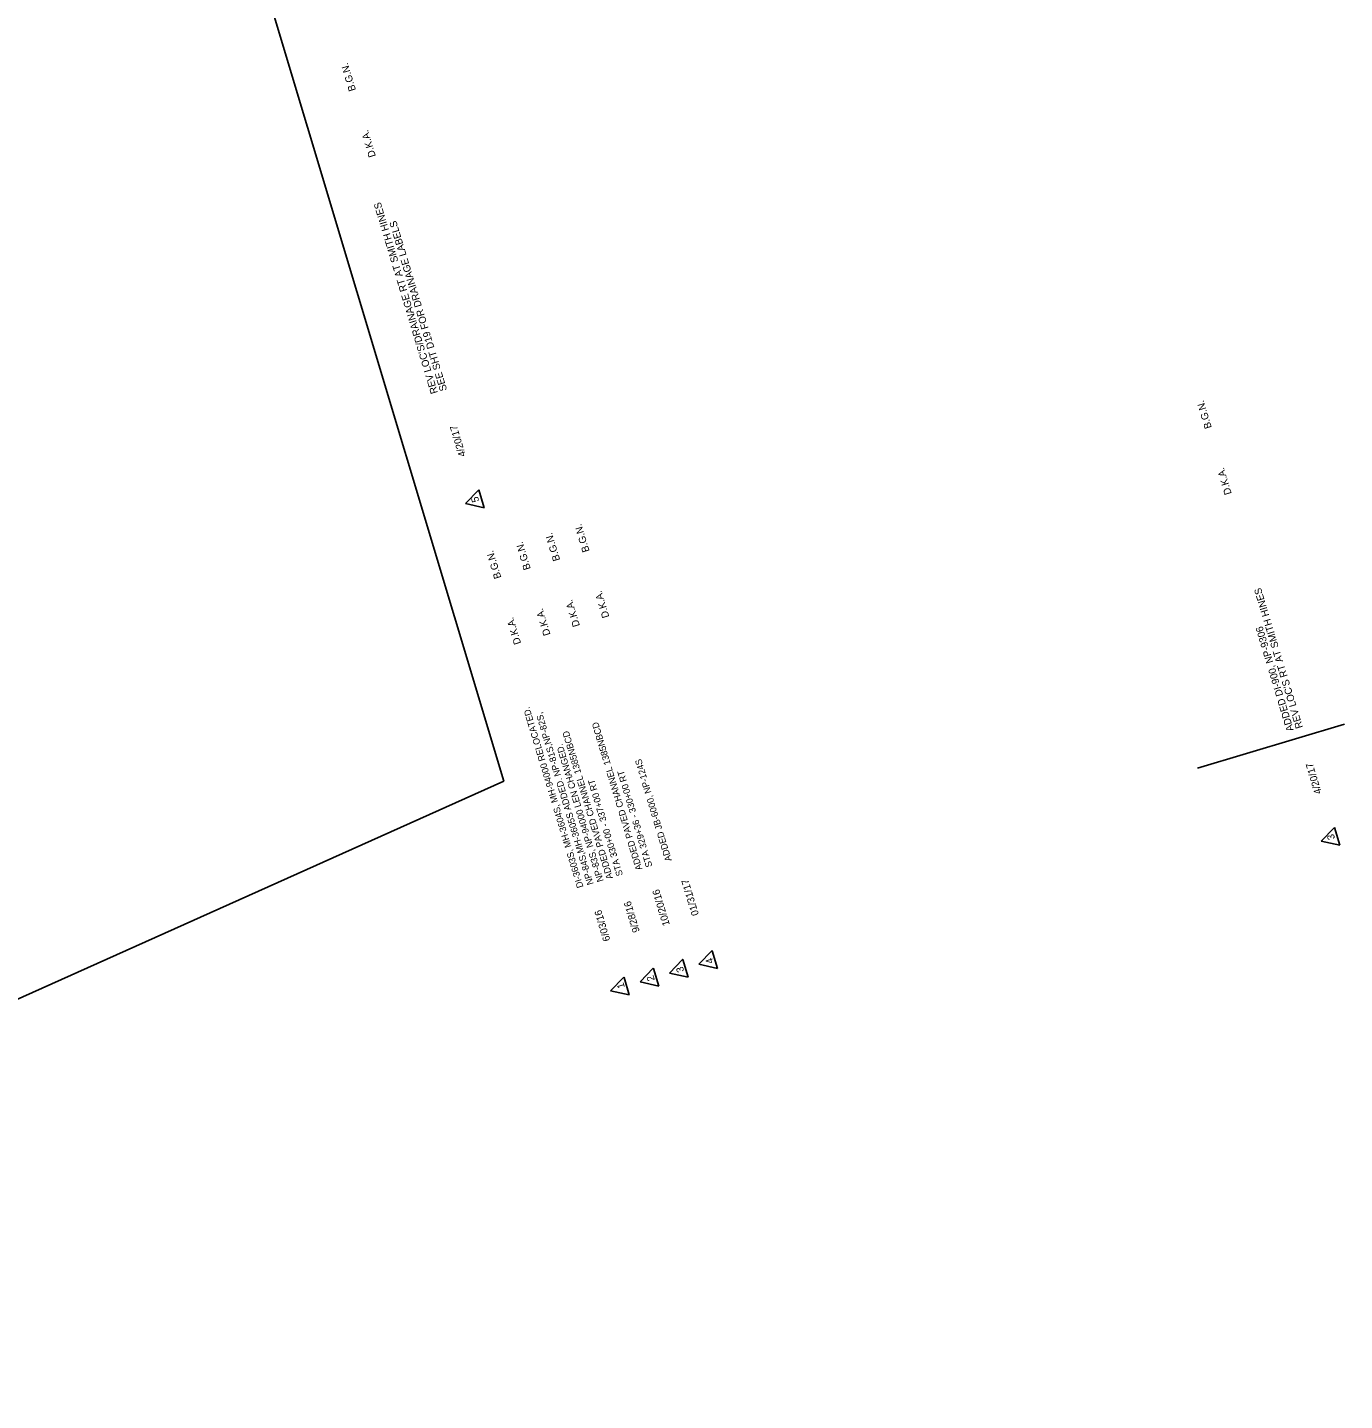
# Model space of a CAD drawing. Extents: x 1612099 to 1613927, y 1087002 to 1088782.
# Drawn here: x 1613125 to 1613927, y 1087002 to 1087838 of the extents above; entities that cross this region are included whole.
import ezdxf

# ---------------------------------------------------------------- set-up
doc = ezdxf.new("R2010")
doc.units = 0
doc.layers.add('RD_HY_Area_XP-Pre sub', color=7, linetype='Continuous')
doc.layers.add('RD_HY_Misc', color=7, linetype='Continuous')

msp = doc.modelspace()

# ---------------------------------------------------------------- linework, layer by layer
at = {"layer": 'RD_HY_Area_XP-Pre sub'}
for p, q in [((1613391.93, 1087547.97), (1613400.01, 1087556.34)), ((1613403.28, 1087545.43), (1613400.01, 1087556.34)), ((1613391.93, 1087547.97), (1613403.28, 1087545.43)), ((1613927.08, 1087413.81), (1613837.54, 1087386.89)), ((1613912.94, 1087342.52), (1613921.02, 1087350.9)), ((1613924.3, 1087339.99), (1613921.02, 1087350.9)), ((1613912.94, 1087342.52), (1613924.3, 1087339.99)), ((1613542.03, 1087275.92), (1613534.01, 1087267.61)), ((1613542.16, 1087275.74), (1613542.03, 1087275.92)), ((1613545.37, 1087265.07), (1613542.16, 1087275.74)), ((1613506.22, 1087265.16), (1613498.19, 1087256.84)), ((1613506.34, 1087264.98), (1613506.22, 1087265.16)), ((1613509.55, 1087254.31), (1613506.34, 1087264.98)), ((1613524.13, 1087270.54), (1613516.1, 1087262.22)), ((1613524.25, 1087270.36), (1613524.13, 1087270.54)), ((1613527.46, 1087259.69), (1613524.25, 1087270.36)), ((1613534.01, 1087267.61), (1613545.37, 1087265.07)), ((1613488.31, 1087259.77), (1613480.28, 1087251.45)), ((1613488.43, 1087259.59), (1613488.31, 1087259.77)), ((1613491.64, 1087248.92), (1613488.43, 1087259.59)), ((1613498.19, 1087256.84), (1613509.55, 1087254.31)), ((1613516.1, 1087262.22), (1613527.46, 1087259.69)), ((1613480.28, 1087251.45), (1613491.64, 1087248.92))]:
    msp.add_line(p, q, dxfattribs=at)
at = {"layer": 'RD_HY_Misc'}
msp.add_lwpolyline([(1612576.55, 1087001.95), (1612843.09, 1087121.93), (1613116.66, 1087245.07), (1613415.21, 1087379.03), (1613026.44, 1088673.77), (1612864.62, 1088666.55), (1612609.21, 1088637.97), (1612610.6, 1088625.86), (1612401.17, 1088591.81), (1612109.16, 1088544.34), (1612170.23, 1088342.42), (1612137.15, 1088332.42), (1612525.19, 1087049.57), (1612547, 1087056.17)], close=True, dxfattribs=at)
msp.add_lwpolyline([(1612576.55, 1087001.95), (1612843.09, 1087121.93), (1613116.66, 1087245.07), (1613415.21, 1087379.03), (1613026.44, 1088673.77), (1612864.62, 1088666.55), (1612609.21, 1088637.97), (1612610.6, 1088625.86), (1612401.17, 1088591.81), (1612109.16, 1088544.34), (1612170.23, 1088342.42), (1612137.15, 1088332.42), (1612525.19, 1087049.57), (1612547, 1087056.17)], close=True, dxfattribs=at)
msp.add_lwpolyline([(1612576.55, 1087001.95), (1612843.09, 1087121.93), (1613116.66, 1087245.07), (1613415.21, 1087379.03), (1613026.44, 1088673.77), (1612864.62, 1088666.55), (1612609.21, 1088637.97), (1612610.6, 1088625.86), (1612401.17, 1088591.81), (1612109.16, 1088544.34), (1612170.23, 1088342.42), (1612137.15, 1088332.42), (1612525.19, 1087049.57), (1612547, 1087056.17)], close=True, dxfattribs=at)
msp.add_lwpolyline([(1612576.55, 1087001.95), (1612843.09, 1087121.93), (1613116.66, 1087245.07), (1613415.21, 1087379.03), (1613026.44, 1088673.77), (1612864.62, 1088666.55), (1612609.21, 1088637.97), (1612610.6, 1088625.86), (1612401.17, 1088591.81), (1612109.16, 1088544.34), (1612170.23, 1088342.42), (1612137.15, 1088332.42), (1612525.19, 1087049.57), (1612547, 1087056.17)], close=True, dxfattribs=at)
msp.add_lwpolyline([(1612576.55, 1087001.95), (1612843.09, 1087121.93), (1613116.66, 1087245.07), (1613415.21, 1087379.03), (1613026.44, 1088673.77), (1612864.62, 1088666.55), (1612609.21, 1088637.97), (1612610.6, 1088625.86), (1612401.17, 1088591.81), (1612109.16, 1088544.34), (1612170.23, 1088342.42), (1612137.15, 1088332.42), (1612525.19, 1087049.57), (1612547, 1087056.17)], close=True, dxfattribs=at)
msp.add_lwpolyline([(1612576.55, 1087001.95), (1612843.09, 1087121.93), (1613116.66, 1087245.07), (1613415.21, 1087379.03), (1613026.44, 1088673.77), (1612864.62, 1088666.55), (1612609.21, 1088637.97), (1612610.6, 1088625.86), (1612401.17, 1088591.81), (1612109.16, 1088544.34), (1612170.23, 1088342.42), (1612137.15, 1088332.42), (1612525.19, 1087049.57), (1612547, 1087056.17)], close=True, dxfattribs=at)
msp.add_lwpolyline([(1612576.55, 1087001.95), (1612843.09, 1087121.93), (1613116.66, 1087245.07), (1613415.21, 1087379.03), (1613026.44, 1088673.77), (1612864.62, 1088666.55), (1612609.21, 1088637.97), (1612610.6, 1088625.86), (1612401.17, 1088591.81), (1612109.16, 1088544.34), (1612170.23, 1088342.42), (1612137.15, 1088332.42), (1612525.19, 1087049.57), (1612547, 1087056.17)], close=True, dxfattribs=at)
msp.add_lwpolyline([(1612576.55, 1087001.95), (1612843.09, 1087121.93), (1613116.66, 1087245.07), (1613415.21, 1087379.03), (1613026.44, 1088673.77), (1612864.62, 1088666.55), (1612609.21, 1088637.97), (1612610.6, 1088625.86), (1612401.17, 1088591.81), (1612109.16, 1088544.34), (1612170.23, 1088342.42), (1612137.15, 1088332.42), (1612525.19, 1087049.57), (1612547, 1087056.17)], close=True, dxfattribs=at)
msp.add_lwpolyline([(1612576.55, 1087001.95), (1612843.09, 1087121.93), (1613116.66, 1087245.07), (1613415.21, 1087379.03), (1613026.44, 1088673.77), (1612864.62, 1088666.55), (1612609.21, 1088637.97), (1612610.6, 1088625.86), (1612401.17, 1088591.81), (1612109.16, 1088544.34), (1612170.23, 1088342.42), (1612137.15, 1088332.42), (1612525.19, 1087049.57), (1612547, 1087056.17)], close=True, dxfattribs=at)

# ---------------------------------------------------------------- texts
at = {"layer": 'RD_HY_Area_XP-Pre sub'}
for s, height, p in [('B.G.N.', 4.4, (1613325.3, 1087799.76)), ('D.K.A.', 4.4, (1613337.39, 1087759.52)), ("REV LOC'S/DRAINAGE RT AT SMITH HINES", 4.4, (1613375.16, 1087615.54)), ('SEE SHT D19 FOR DRAINAGE LABELS', 4.4, (1613380.77, 1087617.23)), ('B.G.N.', 4.4, (1613846.31, 1087594.31)), ('4/20/17', 4.4, (1613392.19, 1087577.27)), ('D.K.A.', 4.4, (1613858.41, 1087554.08)), ('5', 4.4, (1613400.35, 1087549.48)), ('B.G.N.', 4.4, (1613467.52, 1087519.09)), ('B.G.N.', 4.4, (1613431.7, 1087508.32)), ('B.G.N.', 4.4, (1613449.61, 1087513.71)), ('B.G.N.', 4.4, (1613413.8, 1087502.94)), ('D.K.A.', 4.4, (1613479.55, 1087479.07)), ("REV LOC'S RT AT SMITH HINES", 4.4, (1613901.78, 1087411.78)), ('D.K.A.', 4.4, (1613443.74, 1087468.3)), ('D.K.A.', 4.4, (1613461.64, 1087473.69)), ('D.K.A.', 4.4, (1613425.83, 1087462.92)), ('ADDED DI-900, NP-9306', 4.4, (1613896.18, 1087410.1)), ('DI-3603S, MH-3604S, MH-94000 RELOCATED.', 4, (1613463.81, 1087314.68)), ('NP-84S,MH-3605S ADDED. NP-81S,NP-82S, ', 4, (1613469.94, 1087316.52)), ('ADDED PAVED CHANNEL 1385NBCD ', 4, (1613499.63, 1087325.45)), ('ADDED PAVED CHANNEL 1385NBCD ', 4, (1613481.72, 1087320.06)), ('NP-83S, NP-94000 LEN CHANGED. ', 4, (1613476.07, 1087318.36)), ('ADDED JB-6000, NP-124S', 4, (1613517.54, 1087330.83)), ('STA 329+36 - 330+00 RT', 4, (1613505.76, 1087327.29)), ('4/20/17', 4.4, (1613913.21, 1087371.82)), ('STA 330+00 - 337+00 RT', 4, (1613487.85, 1087321.9)), ('3', 4.4, (1613921.37, 1087344.04)), ('01/31/17', 4.4, (1613534.04, 1087297.83)), ('9/28/16', 4.4, (1613498.06, 1087287.6)), ('10/20/16', 4.4, (1613516.37, 1087291.66)), ('6/03/16', 4.4, (1613480.16, 1087282.22)), ('3', 4.4, (1613525.12, 1087263.36)), ('4', 4.4, (1613543.06, 1087268.64)), ('1', 4.4, (1613489.02, 1087253.52)), ('2', 4.4, (1613507.21, 1087257.98))]:
    msp.add_text(s, height=height, rotation=106.73352, dxfattribs=at).set_placement(p)

doc.saveas('drawing.dxf')
